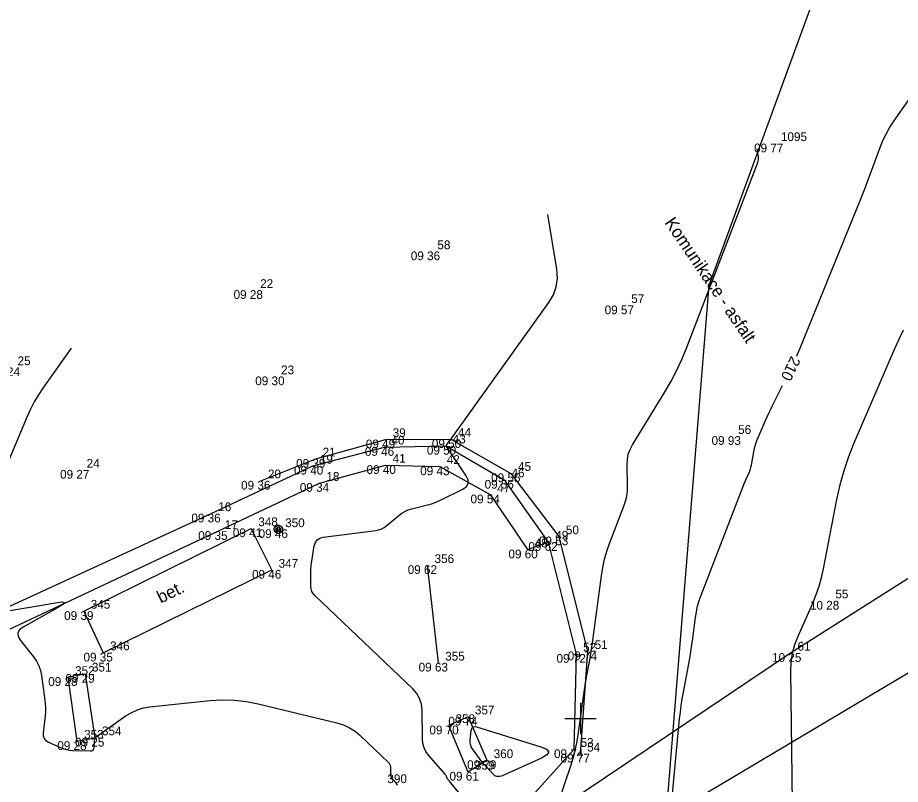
# Model space of a CAD drawing. Extents: x -711234 to -710007, y -1026313 to -1025448.
# Drawn here: x -710993.01 to -710964.77, y -1025877.11 to -1025852.58 of the extents above; entities that cross this region are included whole.
import ezdxf

# ---------------------------------------------------------------- set-up
doc = ezdxf.new("R2010")
doc.units = 0
for name, color, linetype in [('Ex_Contour Labels', 7, 'Continuous'), ('Ex_Major Contours', 7, 'Continuous'), ('Ex_Minor Contours', 7, 'Continuous'), ('Z_betonova_konstrukce', 7, 'Continuous'), ('Z_body', 7, 'Continuous'), ('Z_body_cisla', 7, 'Continuous'), ('Z_body_vysky_redukovane', 7, 'Continuous'), ('Z_hektometricka_sit', 7, 'Continuous'), ('Z_katastr_hranice', 7, 'Continuous'), ('Z_komunikace', 7, 'Continuous'), ('Z_popisy', 7, 'Continuous'), ('Z_reklama', 7, 'Continuous'), ('Z_sloupy', 7, 'Continuous'), ('Z_vdz25_plna', 7, 'Continuous'), ('Z_vdz25_prerusovana', 7, 'Continuous'), ('Z_zlabek', 7, 'Continuous')]:
    doc.layers.add(name, color=color, linetype=linetype)

# ---------------------------------------------------------------- blocks, each defined once
blk = doc.blocks.new('POINT_DISPLAY')
blk.add_line((0, 0), (0, 0))
blk = doc.blocks.new('Z601')
for p, q in [((-0.13, 0.03), (-0.1, 0.08)), ((-0.13, -0.03), (-0.13, 0.03)), ((-0.1, 0.08), (-0.08, 0.1)), ((-0.08, 0.1), (-0.03, 0.13)), ((-0.08, 0.05), (-0.08, -0.05)), ((-0.03, 0.13), (0.03, 0.13)), ((-0.03, -0.08), (-0.03, 0.08)), ((-0.03, 0.08), (0.03, 0.08)), ((0.03, 0.13), (0.08, 0.1)), ((0.03, 0.08), (0.03, -0.08)), ((0.08, 0.1), (0.1, 0.08)), ((0.08, -0.05), (0.08, 0.05)), ((0.1, 0.08), (0.13, 0.03)), ((0.13, 0.03), (0.13, -0.03)), ((-0.1, -0.08), (-0.13, -0.03)), ((-0.08, -0.1), (-0.1, -0.08)), ((-0.08, -0.05), (-0.03, -0.08)), ((-0.03, -0.13), (-0.08, -0.1)), ((0.03, -0.13), (-0.03, -0.13)), ((0.03, -0.08), (0.08, -0.05)), ((0.08, -0.1), (0.03, -0.13)), ((0.1, -0.08), (0.08, -0.1)), ((0.13, -0.03), (0.1, -0.08))]:
    blk.add_line(p, q)

msp = doc.modelspace()

# ---------------------------------------------------------------- linework, layer by layer
at = {"layer": 'Ex_Major Contours'}
for points in [[(-710968.08, -1025863.408), (-710968.07, -1025863.384), (-710967.982, -1025863.173), (-710966.059, -1025858.429), (-710965.973, -1025858.216), (-710965.889, -1025858.001), (-710965.807, -1025857.786), (-710965.726, -1025857.571), (-710965.405, -1025856.707), (-710965.318, -1025856.495), (-710965.219, -1025856.289), (-710965.106, -1025856.09), (-710964.981, -1025855.898), (-710964.12, -1025854.663)], [(-710972.147, -1025878.324), (-710971.831, -1025875.018), (-710971.808, -1025874.803), (-710971.78, -1025874.588), (-710971.748, -1025874.375), (-710971.71, -1025874.162), (-710971.54, -1025873.252), (-710971.507, -1025873.069), (-710971.476, -1025872.885), (-710971.448, -1025872.7), (-710971.423, -1025872.516), (-710971.326, -1025871.776), (-710971.297, -1025871.592), (-710971.256, -1025871.411), (-710971.205, -1025871.233), (-710971.144, -1025871.058), (-710969.812, -1025867.607), (-710969.789, -1025867.548), (-710969.765, -1025867.489), (-710969.74, -1025867.43), (-710969.715, -1025867.372), (-710969.612, -1025867.14), (-710969.588, -1025867.081), (-710969.567, -1025867.022), (-710969.55, -1025866.961), (-710969.536, -1025866.899), (-710969.443, -1025866.413), (-710969.421, -1025866.311), (-710969.393, -1025866.212), (-710969.36, -1025866.114), (-710969.321, -1025866.018), (-710969.086, -1025865.473), (-710969.032, -1025865.351), (-710968.976, -1025865.23), (-710968.919, -1025865.11), (-710968.859, -1025864.99), (-710968.537, -1025864.353)]]:
    msp.add_lwpolyline(points, dxfattribs=at)
at = {"layer": 'Ex_Minor Contours'}
for points in [[(-710975.706, -1025877.682), (-710975.312, -1025876.518), (-710975.237, -1025876.276), (-710975.173, -1025876.031), (-710975.12, -1025875.784), (-710975.079, -1025875.534), (-710974.895, -1025874.224), (-710974.875, -1025874.087), (-710974.854, -1025873.951), (-710974.83, -1025873.814), (-710974.806, -1025873.678), (-710974.704, -1025873.133), (-710974.679, -1025872.997), (-710974.657, -1025872.86), (-710974.636, -1025872.724), (-710974.617, -1025872.586), (-710974.335, -1025870.435), (-710974.293, -1025870.17), (-710974.235, -1025869.91), (-710974.161, -1025869.653), (-710974.072, -1025869.4), (-710973.615, -1025868.214), (-710973.561, -1025868.053), (-710973.524, -1025867.89), (-710973.504, -1025867.724), (-710973.499, -1025867.555), (-710973.513, -1025866.874), (-710973.504, -1025866.707), (-710973.473, -1025866.546), (-710973.419, -1025866.392), (-710973.341, -1025866.243), (-710972.297, -1025864.543), (-710972.102, -1025864.208), (-710971.922, -1025863.864), (-710971.759, -1025863.513), (-710971.611, -1025863.153), (-710969.33, -1025857.211), (-710969.317, -1025857.169), (-710969.31, -1025857.127), (-710969.308, -1025857.084), (-710969.312, -1025857.041), (-710969.356, -1025856.778)], [(-710978.633, -1025877.697), (-710979.206, -1025876.997), (-710979.219, -1025876.981), (-710979.231, -1025876.964), (-710979.242, -1025876.947), (-710979.252, -1025876.929), (-710979.291, -1025876.856), (-710979.301, -1025876.838), (-710979.312, -1025876.821), (-710979.324, -1025876.805), (-710979.337, -1025876.789), (-710979.867, -1025876.171), (-710979.948, -1025876.058), (-710980.007, -1025875.937), (-710980.043, -1025875.808), (-710980.057, -1025875.669), (-710980.07, -1025874.737), (-710980.091, -1025874.542), (-710980.148, -1025874.362), (-710980.241, -1025874.199), (-710980.37, -1025874.051), (-710983.493, -1025871.076), (-710983.551, -1025871.009), (-710983.593, -1025870.935), (-710983.619, -1025870.853), (-710983.628, -1025870.765), (-710983.633, -1025870.397), (-710983.632, -1025870.305), (-710983.627, -1025870.213), (-710983.618, -1025870.122), (-710983.606, -1025870.031), (-710983.517, -1025869.481), (-710983.484, -1025869.373), (-710983.426, -1025869.291), (-710983.342, -1025869.235), (-710983.233, -1025869.207), (-710981.619, -1025869.003), (-710981.502, -1025868.98), (-710981.392, -1025868.942), (-710981.288, -1025868.888), (-710981.192, -1025868.818), (-710980.818, -1025868.509), (-710980.721, -1025868.438), (-710980.619, -1025868.378), (-710980.51, -1025868.331), (-710980.396, -1025868.295), (-710979.893, -1025868.167), (-710979.772, -1025868.132), (-710979.652, -1025868.091), (-710979.535, -1025868.044), (-710979.421, -1025867.99), (-710978.768, -1025867.661), (-710978.652, -1025867.579), (-710978.595, -1025867.482), (-710978.597, -1025867.369), (-710978.659, -1025867.241), (-710979.273, -1025866.335), (-710979.287, -1025866.307), (-710979.291, -1025866.281), (-710979.285, -1025866.254), (-710979.27, -1025866.228), (-710979.19, -1025866.123), (-710979.17, -1025866.096), (-710979.15, -1025866.07), (-710979.131, -1025866.043), (-710979.112, -1025866.016), (-710976.011, -1025861.693), (-710975.866, -1025861.447), (-710975.777, -1025861.188), (-710975.742, -1025860.915), (-710975.763, -1025860.63), (-710976.051, -1025858.882)], [(-710964.685, -1025862.584), (-710964.822, -1025862.88), (-710964.953, -1025863.179), (-710966.255, -1025866.19), (-710966.431, -1025866.63), (-710966.582, -1025867.077), (-710966.708, -1025867.531), (-710966.81, -1025867.993), (-710967.236, -1025870.218), (-710967.299, -1025870.501), (-710967.377, -1025870.778), (-710967.472, -1025871.051), (-710967.582, -1025871.319), (-710968.054, -1025872.38), (-710968.157, -1025872.648), (-710968.229, -1025872.923), (-710968.271, -1025873.203), (-710968.282, -1025873.491), (-710968.227, -1025877.723)], [(-710991.297, -1025863.153), (-710992.199, -1025864.436), (-710992.344, -1025864.653), (-710992.476, -1025864.877), (-710992.596, -1025865.107), (-710992.704, -1025865.345), (-710993.715, -1025867.732)], [(-710993.498, -1025871.588), (-710991.797, -1025871.299), (-710991.597, -1025871.276), (-710991.521, -1025871.297), (-710991.567, -1025871.361), (-710991.737, -1025871.468), (-710992.83, -1025872.078), (-710992.945, -1025872.166), (-710992.998, -1025872.267), (-710992.988, -1025872.38), (-710992.916, -1025872.506), (-710992.501, -1025873.033), (-710992.407, -1025873.169), (-710992.333, -1025873.314), (-710992.28, -1025873.467), (-710992.246, -1025873.629), (-710992.136, -1025874.412), (-710992.122, -1025874.538), (-710992.116, -1025874.664), (-710992.119, -1025874.79), (-710992.129, -1025874.916), (-710992.192, -1025875.465), (-710992.191, -1025875.562), (-710992.162, -1025875.643), (-710992.107, -1025875.709), (-710992.024, -1025875.76), (-710991.64, -1025875.933), (-710991.543, -1025875.971), (-710991.444, -1025875.999), (-710991.342, -1025876.017), (-710991.238, -1025876.026), (-710990.677, -1025876.043), (-710990.63, -1025876.038), (-710990.595, -1025876.019), (-710990.572, -1025875.986), (-710990.562, -1025875.94), (-710990.547, -1025875.727), (-710990.539, -1025875.676), (-710990.52, -1025875.631), (-710990.491, -1025875.592), (-710990.453, -1025875.559), (-710989.531, -1025874.912), (-710989.358, -1025874.806), (-710989.176, -1025874.724), (-710988.985, -1025874.666), (-710988.785, -1025874.633), (-710986.852, -1025874.428), (-710986.463, -1025874.403), (-710986.076, -1025874.412), (-710985.692, -1025874.455), (-710985.309, -1025874.531), (-710982.797, -1025875.142), (-710982.589, -1025875.207), (-710982.395, -1025875.297), (-710982.214, -1025875.412), (-710982.047, -1025875.552), (-710981.158, -1025876.399), (-710981.127, -1025876.434), (-710981.104, -1025876.474), (-710981.09, -1025876.518), (-710981.085, -1025876.565), (-710981.082, -1025876.791), (-710981.079, -1025876.825), (-710981.07, -1025876.856), (-710981.056, -1025876.885), (-710981.036, -1025876.913), (-710980.946, -1025877.018), (-710980.924, -1025877.044), (-710980.904, -1025877.072), (-710980.885, -1025877.101), (-710980.868, -1025877.131)]]:
    msp.add_lwpolyline(points, dxfattribs=at)
msp.add_lwpolyline([(-710978.078, -1025876.482), (-710978.132, -1025876.419), (-710978.183, -1025876.354), (-710978.232, -1025876.287), (-710978.456, -1025875.973), (-710978.495, -1025875.908), (-710978.52, -1025875.84), (-710978.532, -1025875.768), (-710978.53, -1025875.692), (-710978.497, -1025875.383), (-710978.48, -1025875.318), (-710978.447, -1025875.278), (-710978.397, -1025875.263), (-710978.331, -1025875.274), (-710976.276, -1025875.906), (-710976.087, -1025875.987), (-710976.02, -1025876.075), (-710976.076, -1025876.17), (-710976.254, -1025876.273), (-710977.535, -1025876.843), (-710977.609, -1025876.864), (-710977.677, -1025876.863), (-710977.74, -1025876.837), (-710977.799, -1025876.788), (-710978.023, -1025876.544)], close=True, dxfattribs=at)
at = {"layer": 'Z_betonova_konstrukce'}
for p, q in [((-710990.89, -1025871.57), (-710985.54, -1025868.92)), ((-710984.88, -1025870.25), (-710985.54, -1025868.92)), ((-710990.27, -1025872.9), (-710984.88, -1025870.25)), ((-710990.89, -1025871.57), (-710990.27, -1025872.9)), ((-710990.85, -1025873.58), (-710991.4, -1025873.68)), ((-710990.85, -1025873.58), (-710990.54, -1025875.62)), ((-710991.4, -1025873.68), (-710991.11, -1025875.73)), ((-710991.11, -1025875.73), (-710990.54, -1025875.62))]:
    msp.add_line(p, q, dxfattribs=at)
at = {"layer": 'Z_hektometricka_sit'}
for p, q in [((-710975, -1025874.5), (-710975, -1025875.5)), ((-710975.5, -1025875), (-710974.5, -1025875))]:
    msp.add_line(p, q, dxfattribs=at)
at = {"layer": 'Z_katastr_hranice'}
for points in [[(-710937.26, -1025842.82), (-710939.53, -1025844.83), (-710949.1, -1025855.62), (-710957.15, -1025859.01), (-710957.45, -1025861.7), (-710956.04, -1025864.39), (-710951.61, -1025865.47), (-710962.34, -1025872.25), (-710972.26, -1025878.16)], [(-710972.26, -1025878.16), (-710970.89, -1025861.14), (-710964.85, -1025844.62)]]:
    msp.add_lwpolyline(points, dxfattribs=at)
at = {"layer": 'Z_komunikace'}
for p, q in [((-710981.27, -1025866.32), (-710979.31, -1025866.28)), ((-710979.31, -1025866.28), (-710977.44, -1025867.37)), ((-710983.56, -1025866.92), (-710981.27, -1025866.32)), ((-710986.82, -1025868.45), (-710983.56, -1025866.92)), ((-710977.44, -1025867.37), (-710976.04, -1025869.36)), ((-710994.21, -1025871.85), (-710986.82, -1025868.45)), ((-710976.04, -1025869.36), (-710975.14, -1025872.94)), ((-710975.14, -1025872.94), (-710975.22, -1025875.99)), ((-710975.22, -1025875.99), (-710977.06, -1025878.05))]:
    msp.add_line(p, q, dxfattribs=at)
at = {"layer": 'Z_reklama'}
for p, q in [((-710979.55, -1025873.22), (-710979.9, -1025870.1)), ((-710978.6, -1025874.95), (-710979.23, -1025875.23)), ((-710978.6, -1025874.95), (-710978, -1025876.34)), ((-710979.23, -1025875.23), (-710978.61, -1025876.71)), ((-710978.61, -1025876.71), (-710978, -1025876.34))]:
    msp.add_line(p, q, dxfattribs=at)
at = {"layer": 'Z_vdz25_plna'}
for p, q in [((-710983.47, -1025866.7), (-710981.24, -1025866.08)), ((-710981.24, -1025866.08), (-710979.15, -1025866.07)), ((-710979.15, -1025866.07), (-710977.23, -1025867.16)), ((-710985.23, -1025867.4), (-710983.47, -1025866.7)), ((-710977.23, -1025867.16), (-710975.7, -1025869.18)), ((-710975.7, -1025869.18), (-710974.78, -1025872.86)), ((-710974.78, -1025872.86), (-710975.01, -1025876.13))]:
    msp.add_line(p, q, dxfattribs=at)
at = {"layer": 'Z_vdz25_prerusovana'}
for p, q in [((-710961.53, -1025868.63), (-710968.29, -1025872.91)), ((-710968.29, -1025872.91), (-710975.8, -1025877.96))]:
    msp.add_line(p, q, dxfattribs=at)
at = {"layer": 'Z_zlabek'}
for p, q in [((-710983.35, -1025867.47), (-710981.24, -1025866.9)), ((-710981.24, -1025866.9), (-710979.5, -1025866.94)), ((-710979.5, -1025866.94), (-710977.89, -1025867.84)), ((-710986.6, -1025869.01), (-710983.35, -1025867.47)), ((-710977.89, -1025867.84), (-710976.7, -1025869.6)), ((-710994.08, -1025872.53), (-710986.6, -1025869.01)), ((-710976.7, -1025869.6), (-710976.04, -1025869.36))]:
    msp.add_line(p, q, dxfattribs=at)

# ---------------------------------------------------------------- block references
at = {"layer": 'Z_body'}
for p in [(-710968.82, -1025856.61), (-710979.8, -1025860.06), (-710985.47, -1025861.3), (-710973.6, -1025861.79), (-710984.8, -1025864.06), (-710970.18, -1025865.97), (-710981.24, -1025866.08), (-710979.31, -1025866.28), (-710979.15, -1025866.07), (-710981.27, -1025866.32), (-710983.47, -1025866.7), (-710991.02, -1025867.05), (-710983.56, -1025866.92), (-710981.24, -1025866.9), (-710979.5, -1025866.94), (-710985.23, -1025867.4), (-710977.44, -1025867.37), (-710977.23, -1025867.16), (-710983.35, -1025867.47), (-710977.89, -1025867.84), (-710986.82, -1025868.45), (-710986.6, -1025869.01), (-710985.54, -1025868.92), (-710984.67, -1025868.95), (-710976.04, -1025869.36), (-710975.7, -1025869.18), (-710976.7, -1025869.6), (-710979.9, -1025870.1), (-710984.88, -1025870.25), (-710967.08, -1025871.24), (-710990.89, -1025871.57), (-710990.27, -1025872.9), (-710975.14, -1025872.94), (-710974.78, -1025872.86), (-710968.29, -1025872.91), (-710979.55, -1025873.22), (-710990.85, -1025873.58), (-710991.4, -1025873.68), (-710978.6, -1025874.95), (-710979.23, -1025875.23), (-710991.11, -1025875.73), (-710990.54, -1025875.62), (-710975.22, -1025875.99), (-710975.01, -1025876.13), (-710978, -1025876.34), (-710978.61, -1025876.71)]:
    msp.add_blockref('POINT_DISPLAY', p, dxfattribs=at)
at = {"layer": 'Z_sloupy'}
msp.add_blockref('Z601', (-710984.67, -1025868.95), dxfattribs=at)

# ---------------------------------------------------------------- texts
at = {"layer": 'Ex_Contour Labels'}
msp.add_text('210', height=0.35, rotation=244.2326, dxfattribs=at).set_placement((-710968.263, -1025863.385))
at = {"layer": 'Z_body_cisla'}
for s, p in [('1095', (-710968.59, -1025856.53)), ('58', (-710979.58, -1025859.99)), ('22', (-710985.25, -1025861.23)), ('57', (-710973.38, -1025861.71)), ('25', (-710993.01, -1025863.7)), ('23', (-710984.58, -1025863.99)), ('39', (-710981.01, -1025866)), ('44', (-710978.92, -1025865.99)), ('56', (-710969.96, -1025865.9)), ('40', (-710981.05, -1025866.24)), ('43', (-710979.09, -1025866.2)), ('21', (-710983.25, -1025866.62)), ('41', (-710981.01, -1025866.82)), ('24', (-710990.8, -1025866.98)), ('19', (-710983.34, -1025866.85)), ('42', (-710979.28, -1025866.86)), ('45', (-710977, -1025867.08)), ('20', (-710985, -1025867.32)), ('18', (-710983.13, -1025867.4)), ('46', (-710977.21, -1025867.29)), ('47', (-710977.67, -1025867.77)), ('16', (-710986.59, -1025868.37)), ('17', (-710986.38, -1025868.94)), ('348', (-710985.31, -1025868.85)), ('350', (-710984.45, -1025868.88)), ('49', (-710975.81, -1025869.28)), ('50', (-710975.47, -1025869.11)), ('48', (-710976.47, -1025869.53)), ('347', (-710984.66, -1025870.18)), ('356', (-710979.67, -1025870.03)), ('55', (-710966.85, -1025871.16)), ('345', (-710990.67, -1025871.49)), ('346', (-710990.05, -1025872.82)), ('52', (-710974.92, -1025872.86)), ('51', (-710974.55, -1025872.78)), ('61', (-710968.06, -1025872.83)), ('355', (-710979.33, -1025873.15)), ('352', (-710991.17, -1025873.61)), ('351', (-710990.63, -1025873.5)), ('357', (-710978.38, -1025874.87)), ('358', (-710979, -1025875.15)), ('354', (-710990.31, -1025875.54)), ('353', (-710990.88, -1025875.65)), ('53', (-710975, -1025875.91)), ('54', (-710974.79, -1025876.06)), ('360', (-710977.78, -1025876.27)), ('359', (-710978.38, -1025876.64)), ('390', (-710981.18, -1025877.07))]:
    msp.add_text(s, height=0.28, dxfattribs=at).set_placement(p)
at = {"layer": 'Z_body_vysky_redukovane'}
for s, p in [('09 77', (-710969.45, -1025856.89)), ('09 36', (-710980.43, -1025860.34)), ('09 28', (-710986.1, -1025861.58)), ('09 57', (-710974.23, -1025862.07)), ('09 24', (-710993.87, -1025864.05)), ('09 30', (-710985.407, -1025864.34)), ('09 93', (-710970.81, -1025866.25)), ('09 49', (-710981.87, -1025866.36)), ('09 50', (-710979.917, -1025866.56)), ('09 50', (-710979.757, -1025866.35)), ('09 46', (-710981.9, -1025866.6)), ('09 39', (-710984.1, -1025866.98)), ('09 27', (-710991.65, -1025867.33)), ('09 40', (-710984.167, -1025867.2)), ('09 40', (-710981.847, -1025867.18)), ('09 43', (-710980.13, -1025867.22)), ('09 36', (-710985.86, -1025867.68)), ('09 56', (-710978.07, -1025867.65)), ('09 55', (-710977.86, -1025867.44)), ('09 34', (-710983.98, -1025867.75)), ('09 54', (-710978.52, -1025868.12)), ('09 36', (-710987.45, -1025868.73)), ('09 35', (-710987.23, -1025869.29)), ('09 41', (-710986.123, -1025869.2)), ('09 46', (-710985.3, -1025869.23)), ('09 62', (-710976.67, -1025869.64)), ('09 63', (-710976.33, -1025869.46)), ('09 60', (-710977.307, -1025869.88)), ('09 62', (-710980.53, -1025870.38)), ('09 46', (-710985.51, -1025870.53)), ('10 28', (-710967.663, -1025871.52)), ('09 39', (-710991.52, -1025871.85)), ('09 35', (-710990.9, -1025873.18)), ('09 72', (-710975.77, -1025873.22)), ('09 74', (-710975.41, -1025873.14)), ('10 25', (-710968.873, -1025873.19)), ('09 63', (-710980.18, -1025873.5)), ('09 29', (-710991.48, -1025873.86)), ('09 28', (-710992.03, -1025873.96)), ('09 74', (-710979.23, -1025875.23)), ('09 70', (-710979.837, -1025875.51)), ('09 28', (-710991.74, -1025876.01)), ('09 25', (-710991.17, -1025875.9)), ('09 74', (-710975.85, -1025876.27)), ('09 77', (-710975.64, -1025876.41)), ('09 79', (-710978.63, -1025876.62)), ('09 61', (-710979.193, -1025876.99))]:
    msp.add_text(s, height=0.28, dxfattribs=at).set_placement(p)
at = {"layer": 'Z_popisy'}
for s, rotation, p in [('Komunikace - asfalt', 304.2, (-710972.33, -1025859.14)), ('bet.', 26.1, (-710988.43, -1025871.33))]:
    msp.add_text(s, height=0.4, rotation=rotation, dxfattribs=at).set_placement(p)

doc.saveas('drawing.dxf')
